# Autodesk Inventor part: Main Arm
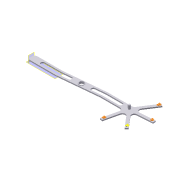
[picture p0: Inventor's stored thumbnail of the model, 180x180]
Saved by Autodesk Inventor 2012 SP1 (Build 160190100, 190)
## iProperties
Created: 2006-09
Part Number: Main Arm
Document SubType Name: Modeling
Material: Aluminum-6061
Mass: 101.819 g
Surface Area: 263.956 cm^2
Volume: 37.5717 cm^3
Density: 2.71 g/cm^3
MajorVersion: 11
MinorVersion: 1
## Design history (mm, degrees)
sketch "Sketch1"
  geometry: L1 (-207, 0)-(276, 0) reference; L2 (-170, 0)-(170, 0); C1 r 10 at (0, 0); C2 r 2.5 at (-170, 0); C3 r 2.5 at (170, 0); 1 further point
  constraints: 3 centre point, 2 end point, 2 point on line, 1 coincident, 1 collinear, 1 equal radius
  dimensions: "d0" = 20 diameter of C1; "d1" = 170 distance of L2.end point (0, 0); "d2" = 170 distance of L2.start point (0, 0); "d18" = 5 diameter of C2
sketch "Sketch2"
  geometry: L1 (0, 0)-(80.01, -7); L2 (80.01, -7)-(180, -7); L3 (-275, 0)-(215, 0) reference; 4 further points
  constraints: 4 end point, 1 coincident, 1 point on line
  dimensions: "d6" = 10 horizontal distance of L2.end point (170, 0); "d10" = 5 deg angle of L1 L3; "d22" = 7 distance between parallel lines of L2 L3
workplane "Work Plane1"
sketch "Sketch3"
  geometry: L1 (-12.5, 2)-(12.5, 2); L2 (12.5, 2)-(12.5, -2); L3 (12.5, -2)-(-12.5, -2); L4 (-12.5, -2)-(-12.5, 2); L5 (-12.5, 2)-(12.5, -2); 3 further points
  constraints: 10 end point, 2 parallel, 1 coincident, 1 horizontal, 1 midpoint, 1 perpendicular
  dimensions: "d7" = 4 distance of L3.end L1.start; "d8" = 25 distance of L1.start L1.end
sweep "Sweep1" sketch "Sketch3" dims "d9" = 0
pattern_circular "Circular Pattern1" dims angle "d24" = 360 deg
extrude "Extrusion1" join sketch "Sketch1" stored distance "d12" = 8; taper "d13" = 0 deg
sketch "Sketch4"
  geometry: C1 r 8 at (0, 0); 1 further point
  constraints: 1 centre point, 1 coincident
  dimensions: "d17" = 16 diameter of C1
extrude "Extrusion2" cut sketch "Sketch4" stored distance "d15" = 10; taper "d16" = 0 deg
sketch "Sketch5"
  geometry: L1 (5.128, 11.375)-(14.872, 13.625); L2 (14.872, 13.625)-(33.768, -68.222); L3 (33.768, -68.222)-(24.024, -70.472); L4 (24.024, -70.472)-(5.128, 11.375); L5 (91.653, -179.862)-(-27.429, 100.677) reference; L6 (6.189, 15.736)-(13.811, 9.264); L7 (13.811, 9.264)-(-40.556, -54.769); L8 (-40.556, -54.769)-(-48.179, -48.296); L9 (-48.179, -48.296)-(6.189, 15.736); L10 (10.32, 17.49)-(9.68, 7.51); L11 (9.68, 7.51)-(-74.148, 12.882); L12 (-74.148, 12.882)-(-73.508, 22.862); L13 (-73.508, 22.862)-(10.32, 17.49); L14 (14.193, 15.223)-(5.807, 9.777); L15 (5.807, 9.777)-(-39.943, 80.225); L16 (-39.943, 80.225)-(-31.556, 85.672); L17 (-31.556, 85.672)-(14.193, 15.223); 6 further points
  constraints: 34 end point, 2 parallel, 1 coincident, 1 midpoint, 1 perpendicular, 31 other
  dimensions: "d27" = 10 deg angle of L2 L5; "d28" = 10 distance of L2.end L3.end; "d31" = 84 distance of L3.end L1.start; "d34" = 160 deg dimension on point (10, 12.5) L14.start L1.start
extrude "Extrusion4" join sketch "Sketch5" stored distance "d29" = 10; taper "d30" = 0 deg
workplane "Work Plane2"
fillet "Fillet1" dims "d36" = 10
fillet "Fillet2" dims "d37" = 10
sketch "Sketch6"
  geometry: C1 r 2.5 at (90.077, 12.5) reference; C2 r 3.995 at (90.077, 12.5); 1 further point
  constraints: 1 centre point, 1 coincident
  dimensions: "d38" = 7.99 diameter of C2
extrude "Extrusion5" join sketch "Sketch6" distance "d39" = 13.25; taper "d40" = 0 deg
sketch "Sketch7"
  geometry: L1 (-140, 6.5)-(-40, 6.5); L2 (-35, 1.5)-(-35, -1.5); L3 (-40, -6.5)-(-140, -6.5); L4 (-145, -1.5)-(-145, 1.5); L5 (-145, 6.5)-(-35, -6.5); L6 (-223.016, 0)-(379.203, 0) reference; L7 (0, 114.484)-(0, -93.963) reference; L8 (145, -1.5)-(145, 1.5); L9 (140, 6.5)-(40, 6.5); L10 (40, -6.5)-(140, -6.5); L11 (35, 1.5)-(35, -1.5); L12 (145, 6.5)-(35, -6.5); A1 r 5 centre (-140, 1.5) between (-140, 6.5) and (-145, 1.5); A2 r 5 centre (-40, 1.5) between (-35, 1.5) and (-40, 6.5); A3 r 5 centre (-40, -1.5) between (-40, -6.5) and (-35, -1.5); A4 r 5 centre (-140, -1.5) between (-145, -1.5) and (-140, -6.5); A5 r 5 centre (140, -1.5) between (140, -6.5) and (145, -1.5); A6 r 5 centre (40, 1.5) between (40, 6.5) and (35, 1.5); A7 r 5 centre (40, -1.5) between (35, -1.5) and (40, -6.5); A8 r 5 centre (140, 1.5) between (145, 1.5) and (140, 6.5); 7 further points
  constraints: 20 end point, 17 point on line, 17 symmetric about line, 16 point on circle, 8 centre point, 8 tangent, 3 equal radius, 2 parallel, 1 horizontal, 1 midpoint, 1 perpendicular, 4 other
  dimensions: "d46" = 13 distance of point (-145, -6.5) L5.start; "d47" = 110 distance of L5.start point (-35, 6.5); "d48" = 5 radius of A1; "d103" = 90 distance from line of point (-90, 0) L7
extrude "Extrusion6" cut sketch "Sketch7" stored distance "d44" = 10; taper "d45" = 0 deg
sketch "Sketch8"
  geometry: L1 (90.077, -12.5)-(135.827, 57.948); L2 (140.02, 55.225)-(131.633, 60.672) reference; C1 r 3.995 at (90.077, -12.5) reference; 2 further points
  constraints: 2 end point, 1 midpoint, 1 point on line
  dimensions: "d50" = 76 distance of point (131.47, 51.239) L1.start
sketch "Sketch9"
  geometry: 1 further point
hole "Hole1" sketch "Sketch9" at (131.47, 51.239) diameter "d51" = 5.5; stored, may be unused: countersink angle "d55" = 90 deg, drill point angle "d57" = 0 deg; dims "d52" = 6, "d53" = 4, "d54" = 2, "d56" = 8
workpoint "Work Point1"
pattern_circular "Circular Pattern2" dims angle "d59" = 160 deg
sketch "Sketch13"
  geometry: 1 further point
hole "Hole5" sketch "Sketch13" at (165.921, -7.64) diameter "d82" = 5.5; stored, may be unused: countersink angle "d86" = 90 deg, drill point angle "d88" = 0 deg; dims "d83" = 6, "d84" = 4, "d85" = 2, "d87" = 8
sketch "Sketch14"
  geometry: 1 further point
hole "Hole6" sketch "Sketch14" at (139.267, -70.434) diameter "d89" = 5.5; stored, may be unused: countersink angle "d93" = 90 deg, drill point angle "d95" = 0 deg; dims "d90" = 6, "d91" = 4, "d92" = 2, "d94" = 8
sketch "Sketch15"
  geometry: 1 further point
hole "Hole7" sketch "Sketch15" at (72.981, -86.552) diameter "d96" = 5.5; stored, may be unused: countersink angle "d100" = 90 deg, drill point angle "d102" = 0 deg; dims "d97" = 6, "d98" = 4, "d99" = 2, "d101" = 8
body "Solid1"
workpoint "Work Point2"
workpoint "Work Point3"
workpoint "Work Point4"
other parameters: "sa_eq_min" = 0.00103, "sa_eq_max" = 73561.5, "sa_pmax_min" = -36347.8, "sa_pmax_max" = 95111.6, "sa_pmin_min" = -96268.2, "sa_pmin_max" = 37174.7, "sa_d_min" = 0, "sa_d_max" = 0.11116, "d21" = 8
